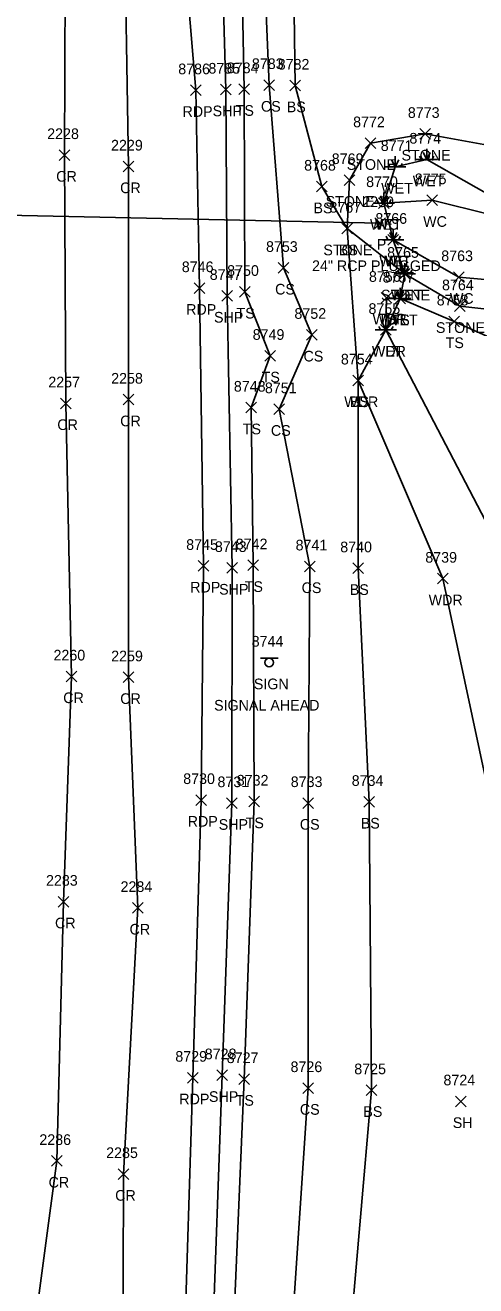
# Model space of a CAD drawing. Extents: x 1462089 to 1464015, y 730534 to 736144.
# Drawn here: x 1463227.5 to 1463312, y 734283.7 to 734520.2 of the extents above; entities that cross this region are included whole.
import ezdxf

# ---------------------------------------------------------------- set-up
doc = ezdxf.new("R2010")
doc.units = 0
for name, color, linetype in [('D_A', 7, 'Continuous'), ('D_C', 7, 'Continuous'), ('D_I', 7, 'Continuous'), ('D_TIC', 7, 'Continuous'), ('DCP', 7, 'Continuous'), ('L_A', 7, 'Continuous'), ('L_I', 7, 'Continuous'), ('L_TIC', 7, 'Continuous'), ('LASF', 7, 'Continuous'), ('LAWA', 7, 'Continuous'), ('LAWE', 7, 'Continuous'), ('LELB', 7, 'Continuous'), ('LWET', 7, 'Continuous'), ('P_A', 7, 'Continuous'), ('P_I', 7, 'Continuous'), ('P_TIC', 7, 'Continuous'), ('PET', 7, 'Continuous'), ('PRC', 7, 'Continuous'), ('PSP', 7, 'Continuous'), ('S_A', 7, 'Continuous'), ('S_C', 7, 'Continuous'), ('S_I', 7, 'Continuous'), ('SSGN', 7, 'Continuous')]:
    doc.layers.add(name, color=color, linetype=linetype)

msp = doc.modelspace()

# ---------------------------------------------------------------- linework, layer by layer
at = {"layer": 'D_TIC'}
for points in [[(1463293.08, 734482.09), (1463295.08, 734484.09)], [(1463295.08, 734482.09), (1463293.08, 734484.09)]]:
    msp.add_lwpolyline(points, dxfattribs=at)
at = {"layer": 'DCP'}
msp.add_lwpolyline([(1463294.08, 734483.09), (1463209.32, 734484.87)], dxfattribs=at)
at = {"layer": 'L_TIC'}
for points in [[(1463267.59, 734507.22), (1463269.59, 734509.22)], [(1463269.59, 734507.22), (1463267.59, 734509.22)], [(1463272.3, 734508), (1463274.3, 734510)], [(1463274.3, 734508), (1463272.3, 734510)], [(1463277.14, 734507.89), (1463279.14, 734509.89)], [(1463279.14, 734507.89), (1463277.14, 734509.89)], [(1463301.55, 734498.83), (1463303.55, 734500.83)], [(1463303.55, 734498.83), (1463301.55, 734500.83)], [(1463291.29, 734497.08), (1463293.29, 734499.08)], [(1463293.29, 734497.08), (1463291.29, 734499.08)], [(1463282.15, 734488.94), (1463284.15, 734490.94)], [(1463284.15, 734488.94), (1463282.15, 734490.94)], [(1463287.33, 734490.17), (1463289.33, 734492.17)], [(1463289.33, 734490.17), (1463287.33, 734492.17)], [(1463293.81, 734485.85), (1463295.81, 734487.85)], [(1463295.81, 734485.85), (1463293.81, 734487.85)], [(1463302.85, 734486.39), (1463304.85, 734488.39)], [(1463304.85, 734486.39), (1463302.85, 734488.39)], [(1463286.89, 734481.05), (1463288.89, 734483.05)], [(1463288.89, 734481.05), (1463286.89, 734483.05)], [(1463286.89, 734481.05), (1463288.89, 734483.05)], [(1463288.89, 734481.05), (1463286.89, 734483.05)], [(1463295.56, 734478.96), (1463297.56, 734480.96)], [(1463297.56, 734478.96), (1463295.56, 734480.96)], [(1463274.95, 734473.69), (1463276.95, 734475.69)], [(1463276.95, 734473.69), (1463274.95, 734475.69)], [(1463297.72, 734472.58), (1463299.72, 734474.58)], [(1463299.72, 734472.58), (1463297.72, 734474.58)], [(1463307.86, 734471.95), (1463309.86, 734473.95)], [(1463309.86, 734471.95), (1463307.86, 734473.95)], [(1463267.74, 734469.19), (1463269.74, 734471.19)], [(1463269.74, 734469.19), (1463267.74, 734471.19)], [(1463294.3, 734468.07), (1463296.3, 734470.07)], [(1463296.3, 734468.07), (1463294.3, 734470.07)], [(1463294.3, 734468.07), (1463296.3, 734470.07)], [(1463296.3, 734468.07), (1463294.3, 734470.07)], [(1463296.82, 734467.93), (1463298.82, 734469.93)], [(1463298.82, 734467.93), (1463296.82, 734469.93)], [(1463308.01, 734466.49), (1463310.01, 734468.49)], [(1463310.01, 734466.49), (1463308.01, 734468.49)], [(1463306.97, 734463.64), (1463308.97, 734465.64)], [(1463308.97, 734463.64), (1463306.97, 734465.64)], [(1463280.28, 734461.13), (1463282.28, 734463.13)], [(1463282.28, 734461.13), (1463280.28, 734463.13)], [(1463294.17, 734462.05), (1463296.17, 734464.05)], [(1463296.17, 734462.05), (1463294.17, 734464.05)], [(1463272.46, 734457.19), (1463274.46, 734459.19)], [(1463274.46, 734457.19), (1463272.46, 734459.19)], [(1463288.99, 734452.57), (1463290.99, 734454.57)], [(1463290.99, 734452.57), (1463288.99, 734454.57)], [(1463288.99, 734452.57), (1463290.99, 734454.57)], [(1463290.99, 734452.57), (1463288.99, 734454.57)], [(1463268.92, 734447.47), (1463270.92, 734449.47)], [(1463270.92, 734447.47), (1463268.92, 734449.47)], [(1463274.17, 734447.18), (1463276.17, 734449.18)], [(1463276.17, 734447.18), (1463274.17, 734449.18)], [(1463269.28, 734417.89), (1463271.28, 734419.89)], [(1463271.28, 734417.89), (1463269.28, 734419.89)], [(1463279.93, 734417.68), (1463281.93, 734419.68)], [(1463281.93, 734417.68), (1463279.93, 734419.68)], [(1463288.96, 734417.33), (1463290.96, 734419.33)], [(1463290.96, 734417.33), (1463288.96, 734419.33)], [(1463304.83, 734415.38), (1463306.83, 734417.38)], [(1463306.83, 734415.38), (1463304.83, 734417.38)], [(1463269.46, 734373.56), (1463271.46, 734375.56)], [(1463271.46, 734373.56), (1463269.46, 734375.56)], [(1463279.59, 734373.28), (1463281.59, 734375.28)], [(1463281.59, 734373.28), (1463279.59, 734375.28)], [(1463291.02, 734373.5), (1463293.02, 734375.5)], [(1463293.02, 734373.5), (1463291.02, 734375.5)], [(1463267.59, 734321.49), (1463269.59, 734323.49)], [(1463269.59, 734321.49), (1463267.59, 734323.49)], [(1463279.6, 734319.8), (1463281.6, 734321.8)], [(1463281.6, 734319.8), (1463279.6, 734321.8)], [(1463291.5, 734319.4), (1463293.5, 734321.4)], [(1463293.5, 734319.4), (1463291.5, 734321.4)], [(1463308.22, 734317.31), (1463310.22, 734319.31)], [(1463310.22, 734317.31), (1463308.22, 734319.31)]]:
    msp.add_lwpolyline(points, dxfattribs=at)
at = {"layer": 'LASF'}
msp.add_lwpolyline([(1463323.69, 734465.88), (1463309.01, 734467.49), (1463298.72, 734473.58), (1463287.89, 734482.05), (1463288.33, 734491.17), (1463292.29, 734498.08), (1463302.55, 734499.83), (1463324.54, 734495.82)], dxfattribs=at)
at = {"layer": 'LAWA'}
msp.add_lwpolyline([(1463328.5, 734104.11), (1463314.12, 734090.85), (1463302.24, 734116.62), (1463309.33, 734167.07), (1463305.62, 734210.31), (1463299.77, 734260.67), (1463318.7, 734272.19), (1463314.85, 734295.69), (1463330.54, 734318.54), (1463330.49, 734348.24), (1463315.46, 734371.33), (1463305.83, 734416.38), (1463289.99, 734453.57), (1463295.17, 734463.05), (1463295.3, 734469.07)], dxfattribs=at)
at = {"layer": 'LAWE'}
for points in [[(1463294.81, 734486.85), (1463303.85, 734487.39), (1463325.96, 734481.92)], [(1463328.35, 734471.18), (1463308.86, 734472.95), (1463296.56, 734479.96)]]:
    msp.add_lwpolyline(points, dxfattribs=at)
at = {"layer": 'LELB'}
for points in [[(1463257.99, 733966.71), (1463259.97, 734009.79), (1463260.85, 734065.09), (1463262.42, 734118.18), (1463263.13, 734164.3), (1463264.61, 734217.86), (1463266.34, 734269.39), (1463268.59, 734322.49), (1463270.46, 734374.56), (1463270.28, 734418.89), (1463269.92, 734448.47), (1463273.46, 734458.19), (1463268.74, 734470.19), (1463268.59, 734508.22), (1463267.59, 734558.75), (1463266.05, 734609.64), (1463265.18, 734660.46), (1463264.37, 734673.7), (1463264.44, 734721.41), (1463263.51, 734771.24)], [(1463265.19, 733966.28), (1463265.78, 734009.31), (1463269.75, 734065.14), (1463271.38, 734117.71), (1463273.22, 734165), (1463277.32, 734216.35), (1463277.15, 734269.17), (1463280.6, 734320.8), (1463280.59, 734374.28), (1463280.93, 734418.68), (1463275.17, 734448.18), (1463281.28, 734462.13), (1463275.95, 734474.69), (1463273.3, 734509), (1463271.21, 734558.82), (1463270.4, 734603.91), (1463269.5, 734660.22), (1463269.15, 734674.46), (1463268.7, 734688.89), (1463268.89, 734721.54), (1463269.27, 734771.05)], [(1463275.52, 734034.35), (1463282.75, 734064.48), (1463283.26, 734113.05), (1463287.02, 734165), (1463290.21, 734212.93), (1463288.11, 734269.86), (1463292.5, 734320.4), (1463292.02, 734374.5), (1463289.96, 734418.33), (1463289.99, 734453.57), (1463287.89, 734482.05), (1463283.15, 734489.94), (1463278.14, 734508.89), (1463277.49, 734559.23), (1463278.42, 734603.31), (1463275.85, 734651.26), (1463277.33, 734664.39), (1463273.56, 734674.46), (1463272.19, 734688.18), (1463274.44, 734722.02), (1463275.24, 734770.64)], [(1463295.3, 734469.07), (1463297.82, 734468.93), (1463307.97, 734464.64), (1463325.57, 734456.76)]]:
    msp.add_lwpolyline(points, dxfattribs=at)
at = {"layer": 'LWET'}
for p, q in [((1463296.91, 734493.62), (1463296.24, 734494.95)), ((1463296.91, 734493.62), (1463296.91, 734495.62)), ((1463296.91, 734493.62), (1463297.57, 734494.95)), ((1463304.84, 734495.01), (1463300.84, 734495.01)), ((1463301.84, 734495.01), (1463301.5, 734495.68)), ((1463302.84, 734495.01), (1463302.17, 734496.34)), ((1463302.84, 734495.01), (1463302.84, 734497.01)), ((1463302.84, 734495.01), (1463303.5, 734496.34)), ((1463303.84, 734495.01), (1463304.17, 734495.68)), ((1463298.91, 734493.62), (1463294.91, 734493.62)), ((1463295.91, 734493.62), (1463295.57, 734494.28)), ((1463297.91, 734493.62), (1463298.24, 734494.28)), ((1463294.81, 734486.85), (1463294.15, 734488.18)), ((1463294.81, 734486.85), (1463294.81, 734488.85)), ((1463294.81, 734486.85), (1463295.48, 734488.18)), ((1463296.81, 734486.85), (1463292.81, 734486.85)), ((1463293.81, 734486.85), (1463293.48, 734487.52)), ((1463295.81, 734486.85), (1463296.15, 734487.52)), ((1463295.56, 734479.96), (1463295.23, 734480.63)), ((1463296.56, 734479.96), (1463295.89, 734481.3)), ((1463296.56, 734479.96), (1463296.56, 734481.96)), ((1463296.56, 734479.96), (1463297.23, 734481.3)), ((1463297.56, 734479.96), (1463297.89, 734480.63)), ((1463298.56, 734479.96), (1463294.56, 734479.96)), ((1463300.72, 734473.58), (1463296.72, 734473.58)), ((1463297.72, 734473.58), (1463297.39, 734474.25)), ((1463298.72, 734473.58), (1463298.05, 734474.92)), ((1463298.72, 734473.58), (1463298.72, 734475.58)), ((1463298.72, 734473.58), (1463299.39, 734474.92)), ((1463299.72, 734473.58), (1463300.05, 734474.25)), ((1463299.82, 734468.93), (1463295.82, 734468.93)), ((1463296.82, 734468.93), (1463296.48, 734469.6)), ((1463297.82, 734468.93), (1463297.15, 734470.27)), ((1463297.82, 734468.93), (1463297.82, 734470.93)), ((1463297.82, 734468.93), (1463298.48, 734470.27)), ((1463298.82, 734468.93), (1463299.15, 734469.6)), ((1463295.17, 734463.05), (1463294.51, 734464.38)), ((1463295.17, 734463.05), (1463295.17, 734465.05)), ((1463295.17, 734463.05), (1463295.84, 734464.38)), ((1463297.17, 734463.05), (1463293.17, 734463.05)), ((1463294.17, 734463.05), (1463293.84, 734463.71)), ((1463296.17, 734463.05), (1463296.51, 734463.71))]:
    msp.add_line(p, q, dxfattribs=at)
msp.add_lwpolyline([(1463337.34, 734378.18), (1463318.38, 734418.58), (1463295.17, 734463.05), (1463297.82, 734468.93), (1463298.72, 734473.58), (1463296.56, 734479.96), (1463294.81, 734486.85), (1463296.91, 734493.62), (1463302.84, 734495.01), (1463325.96, 734481.92)], dxfattribs=at)
at = {"layer": 'P_TIC'}
for points in [[(1463258.54, 734507.02), (1463260.54, 734509.02)], [(1463260.54, 734507.02), (1463258.54, 734509.02)], [(1463264.15, 734507.14), (1463266.15, 734509.14)], [(1463266.15, 734507.14), (1463264.15, 734509.14)], [(1463233.91, 734494.86), (1463235.91, 734496.86)], [(1463235.91, 734494.86), (1463233.91, 734496.86)], [(1463245.89, 734492.71), (1463247.89, 734494.71)], [(1463247.89, 734492.71), (1463245.89, 734494.71)], [(1463259.22, 734469.89), (1463261.22, 734471.89)], [(1463261.22, 734469.89), (1463259.22, 734471.89)], [(1463264.4, 734468.43), (1463266.4, 734470.43)], [(1463266.4, 734468.43), (1463264.4, 734470.43)], [(1463234.12, 734448.27), (1463236.12, 734450.27)], [(1463236.12, 734448.27), (1463234.12, 734450.27)], [(1463245.91, 734448.97), (1463247.91, 734450.97)], [(1463247.91, 734448.97), (1463245.91, 734450.97)], [(1463259.98, 734417.78), (1463261.98, 734419.78)], [(1463261.98, 734417.78), (1463259.98, 734419.78)], [(1463265.36, 734417.39), (1463267.36, 734419.39)], [(1463267.36, 734417.39), (1463265.36, 734419.39)], [(1463235.23, 734397.03), (1463237.23, 734399.03)], [(1463237.23, 734397.03), (1463235.23, 734399.03)], [(1463245.92, 734396.87), (1463247.92, 734398.87)], [(1463247.92, 734396.87), (1463245.92, 734398.87)], [(1463259.51, 734373.85), (1463261.51, 734375.85)], [(1463261.51, 734373.85), (1463259.51, 734375.85)], [(1463265.28, 734373.26), (1463267.28, 734375.26)], [(1463267.28, 734373.26), (1463265.28, 734375.26)], [(1463233.69, 734354.77), (1463235.69, 734356.77)], [(1463235.69, 734354.77), (1463233.69, 734356.77)], [(1463247.67, 734353.6), (1463249.67, 734355.6)], [(1463249.67, 734353.6), (1463247.67, 734355.6)], [(1463257.94, 734321.75), (1463259.94, 734323.75)], [(1463259.94, 734321.75), (1463257.94, 734323.75)], [(1463263.46, 734322.21), (1463265.46, 734324.21)], [(1463265.46, 734322.21), (1463263.46, 734324.21)], [(1463232.49, 734306.13), (1463234.49, 734308.13)], [(1463234.49, 734306.13), (1463232.49, 734308.13)], [(1463244.97, 734303.67), (1463246.97, 734305.67)], [(1463246.97, 734303.67), (1463244.97, 734305.67)]]:
    msp.add_lwpolyline(points, dxfattribs=at)
at = {"layer": 'PET'}
msp.add_lwpolyline([(1463248.8, 733967.1), (1463249.86, 734010.39), (1463251.61, 734064.59), (1463253.36, 734118.27), (1463254.42, 734163.74), (1463255.79, 734217.97), (1463257.3, 734268.95), (1463258.94, 734322.75), (1463260.51, 734374.85), (1463260.98, 734418.78), (1463260.22, 734470.89), (1463259.54, 734508.02), (1463255.84, 734551.94), (1463257.25, 734609.15), (1463256.38, 734661.33), (1463256.42, 734674.99), (1463255.03, 734720.12), (1463254.12, 734771.84)], dxfattribs=at)
at = {"layer": 'PRC'}
for points in [[(1463228.58, 734798.08), (1463230.75, 734747.1), (1463230.44, 734700.4), (1463232, 734654.41), (1463233.92, 734599.45), (1463235.11, 734543.95), (1463234.91, 734495.86), (1463235.12, 734449.27), (1463236.23, 734398.03), (1463234.69, 734355.77), (1463233.49, 734307.13), (1463228.69, 734271.55), (1463231.41, 734217.81), (1463230.21, 734171), (1463228.59, 734116.25), (1463226.96, 734072.96), (1463226.23, 734016.91), (1463224.48, 733963.11)], [(1463241.52, 734797.52), (1463242.3, 734746.35), (1463243.09, 734699.96), (1463244.11, 734654.62), (1463245.06, 734598.2), (1463246.1, 734543.33), (1463246.89, 734493.71), (1463246.91, 734449.97), (1463246.92, 734397.87), (1463248.67, 734354.6), (1463245.97, 734304.67), (1463245.84, 734264.62), (1463244.04, 734215.96), (1463241.66, 734164.25), (1463240.71, 734114.74), (1463238.65, 734070.53), (1463237.77, 734016.4), (1463235.71, 733961.6)]]:
    msp.add_lwpolyline(points, dxfattribs=at)
at = {"layer": 'PSP'}
msp.add_lwpolyline([(1463255.54, 733966.95), (1463256.55, 734009.92), (1463257.79, 734064.75), (1463259.66, 734118.57), (1463259.79, 734164.74), (1463261.4, 734217.95), (1463262.55, 734269.57), (1463264.46, 734323.21), (1463266.28, 734374.26), (1463266.36, 734418.39), (1463265.4, 734469.43), (1463265.15, 734508.14), (1463263.72, 734558.7), (1463262.93, 734609.26), (1463261.91, 734661.14), (1463261.74, 734674.67), (1463260.61, 734721.09), (1463259.81, 734771.37)], dxfattribs=at)
at = {"layer": 'SSGN'}
for p, q in [((1463271.63, 734401.48), (1463274.96, 734401.48)), ((1463273.28, 734400.65), (1463273.28, 734400.65))]:
    msp.add_line(p, q, dxfattribs=at)
msp.add_circle((1463273.28, 734400.65), 0.833, dxfattribs=at)

# ---------------------------------------------------------------- texts
at = {"layer": 'D_A'}
msp.add_text('P', height=2, dxfattribs=at).set_placement((1463293.46, 734478.09))
at = {"layer": 'D_C'}
msp.add_text('24" RCP PLUGGED', height=2, dxfattribs=at).set_placement((1463281.32, 734474.09))
at = {"layer": 'D_I'}
msp.add_text('2230', height=2, dxfattribs=at).set_placement((1463290.74, 734486.09))
at = {"layer": 'L_A'}
for s, p in [('TS', (1463267, 734503.22)), ('CS', (1463271.74, 734504)), ('BS', (1463276.58, 734503.89)), ('STONE', (1463287.83, 734493.08)), ('STONE', (1463298.1, 734494.83)), ('WET', (1463294.29, 734488.62)), ('WET', (1463300.21, 734490.01)), ('STONE', (1463283.87, 734486.17)), ('BS', (1463281.59, 734484.94)), ('WET', (1463292.19, 734481.85)), ('WC', (1463293.12, 734481.85)), ('WC', (1463302.16, 734482.39)), ('STONE', (1463283.44, 734477.05)), ('BS', (1463286.34, 734477.05)), ('WET', (1463293.94, 734474.96)), ('WC', (1463294.87, 734474.96)), ('CS', (1463274.39, 734469.69)), ('STONE', (1463294.26, 734468.58)), ('WET', (1463296.1, 734468.58)), ('WC', (1463307.17, 734467.95)), ('TS', (1463267.15, 734465.19)), ('WDR', (1463292.67, 734464.07)), ('TS', (1463293.71, 734464.07)), ('WET', (1463295.2, 734463.93)), ('TS', (1463296.23, 734463.93)), ('STONE', (1463304.55, 734462.49)), ('WDR', (1463292.54, 734458.05)), ('WET', (1463292.55, 734458.05)), ('TS', (1463306.38, 734459.64)), ('CS', (1463279.72, 734457.13)), ('TS', (1463271.87, 734453.19)), ('WDR', (1463287.36, 734448.57)), ('BS', (1463288.43, 734448.57)), ('TS', (1463268.33, 734443.47)), ('CS', (1463273.61, 734443.18)), ('TS', (1463268.69, 734413.89)), ('CS', (1463279.37, 734413.68)), ('BS', (1463288.4, 734413.33)), ('WDR', (1463303.19, 734411.38)), ('TS', (1463268.87, 734369.56)), ('CS', (1463279.03, 734369.28)), ('BS', (1463290.46, 734369.5)), ('TS', (1463267, 734317.49)), ('CS', (1463279.04, 734315.8)), ('BS', (1463290.94, 734315.4)), ('SH', (1463307.71, 734313.31))]:
    msp.add_text(s, height=2, dxfattribs=at).set_placement(p)
at = {"layer": 'L_I'}
for s, p in [('8783', (1463270.04, 734512)), ('8782', (1463274.88, 734511.89)), ('8784', (1463265.33, 734511.22)), ('8773', (1463299.29, 734502.83)), ('8772', (1463289.03, 734501.08)), ('8774', (1463299.58, 734498.01)), ('8771', (1463294.21, 734496.62)), ('8768', (1463279.84, 734492.94)), ('8769', (1463285.02, 734494.17)), ('8770', (1463291.47, 734489.85)), ('8770', (1463291.47, 734489.85)), ('8775', (1463300.59, 734490.39)), ('8767', (1463284.59, 734485.05)), ('8767', (1463284.59, 734485.05)), ('8766', (1463293.2, 734482.96)), ('8766', (1463293.2, 734482.96)), ('8753', (1463272.69, 734477.69)), ('8765', (1463295.41, 734476.58)), ('8765', (1463295.41, 734476.58)), ('8763', (1463305.55, 734475.95)), ('8750', (1463265.4, 734473.19)), ('8756', (1463291.99, 734472.07)), ('8756', (1463291.99, 734472.07)), ('8757', (1463294.56, 734471.93)), ('8757', (1463294.56, 734471.93)), ('8764', (1463305.7, 734470.49)), ('8758', (1463304.71, 734467.64)), ('8752', (1463278.02, 734465.13)), ('8755', (1463291.91, 734466.05)), ('8755', (1463291.91, 734466.05)), ('8749', (1463270.19, 734461.19)), ('8754', (1463286.73, 734456.57)), ('8754', (1463286.73, 734456.57)), ('8748', (1463266.66, 734451.47)), ('8751', (1463272.48, 734451.18)), ('8742', (1463267.02, 734421.89)), ('8741', (1463278.24, 734421.68)), ('8740', (1463286.61, 734421.33)), ('8739', (1463302.56, 734419.38)), ('8732', (1463267.2, 734377.56)), ('8733', (1463277.33, 734377.28)), ('8734', (1463288.76, 734377.5)), ('8727', (1463265.33, 734325.49)), ('8726', (1463277.29, 734323.8)), ('8725', (1463289.24, 734323.4)), ('8724', (1463305.97, 734321.31))]:
    msp.add_text(s, height=2, dxfattribs=at).set_placement(p)
at = {"layer": 'P_A'}
for s, p in [('RDP', (1463257.03, 734503.02)), ('SHP', (1463262.68, 734503.14)), ('CR', (1463233.34, 734490.86)), ('CR', (1463245.33, 734488.71)), ('RDP', (1463257.71, 734465.89)), ('SHP', (1463262.94, 734464.43)), ('CR', (1463233.55, 734444.27)), ('CR', (1463245.34, 734444.97)), ('RDP', (1463258.47, 734413.78)), ('SHP', (1463263.9, 734413.39)), ('CR', (1463234.66, 734393.03)), ('CR', (1463245.35, 734392.87)), ('RDP', (1463258, 734369.85)), ('SHP', (1463263.82, 734369.26)), ('CR', (1463233.12, 734350.77)), ('CR', (1463247.1, 734349.6)), ('SHP', (1463261.99, 734318.21)), ('RDP', (1463256.43, 734317.75)), ('CR', (1463231.92, 734302.13)), ('CR', (1463244.4, 734299.67))]:
    msp.add_text(s, height=2, dxfattribs=at).set_placement(p)
at = {"layer": 'P_I'}
for s, p in [('8786', (1463256.23, 734511.02)), ('8785', (1463261.89, 734511.14)), ('2228', (1463231.65, 734498.86)), ('2229', (1463243.63, 734496.71)), ('8746', (1463256.9, 734473.89)), ('8747', (1463262.14, 734472.43)), ('2258', (1463243.65, 734452.97)), ('2257', (1463231.86, 734452.27)), ('8745', (1463257.72, 734421.78)), ('8743', (1463263.1, 734421.39)), ('2260', (1463232.83, 734401.03)), ('2259', (1463243.65, 734400.87)), ('8730', (1463257.16, 734377.85)), ('8731', (1463263.59, 734377.26)), ('2283', (1463231.43, 734358.77)), ('2284', (1463245.41, 734357.6)), ('8729', (1463255.68, 734325.75)), ('8728', (1463261.2, 734326.21)), ('2286', (1463230.18, 734310.13)), ('2285', (1463242.71, 734307.67))]:
    msp.add_text(s, height=2, dxfattribs=at).set_placement(p)
at = {"layer": 'S_A'}
msp.add_text('SIGN', height=2, dxfattribs=at).set_placement((1463270.41, 734395.63))
at = {"layer": 'S_C'}
msp.add_text('SIGNAL AHEAD', height=2, dxfattribs=at).set_placement((1463262.95, 734391.63))
at = {"layer": 'S_I'}
msp.add_text('8744', height=2, dxfattribs=at).set_placement((1463270, 734403.63))

doc.saveas('drawing.dxf')
